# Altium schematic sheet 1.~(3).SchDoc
size 420 x 297 mm
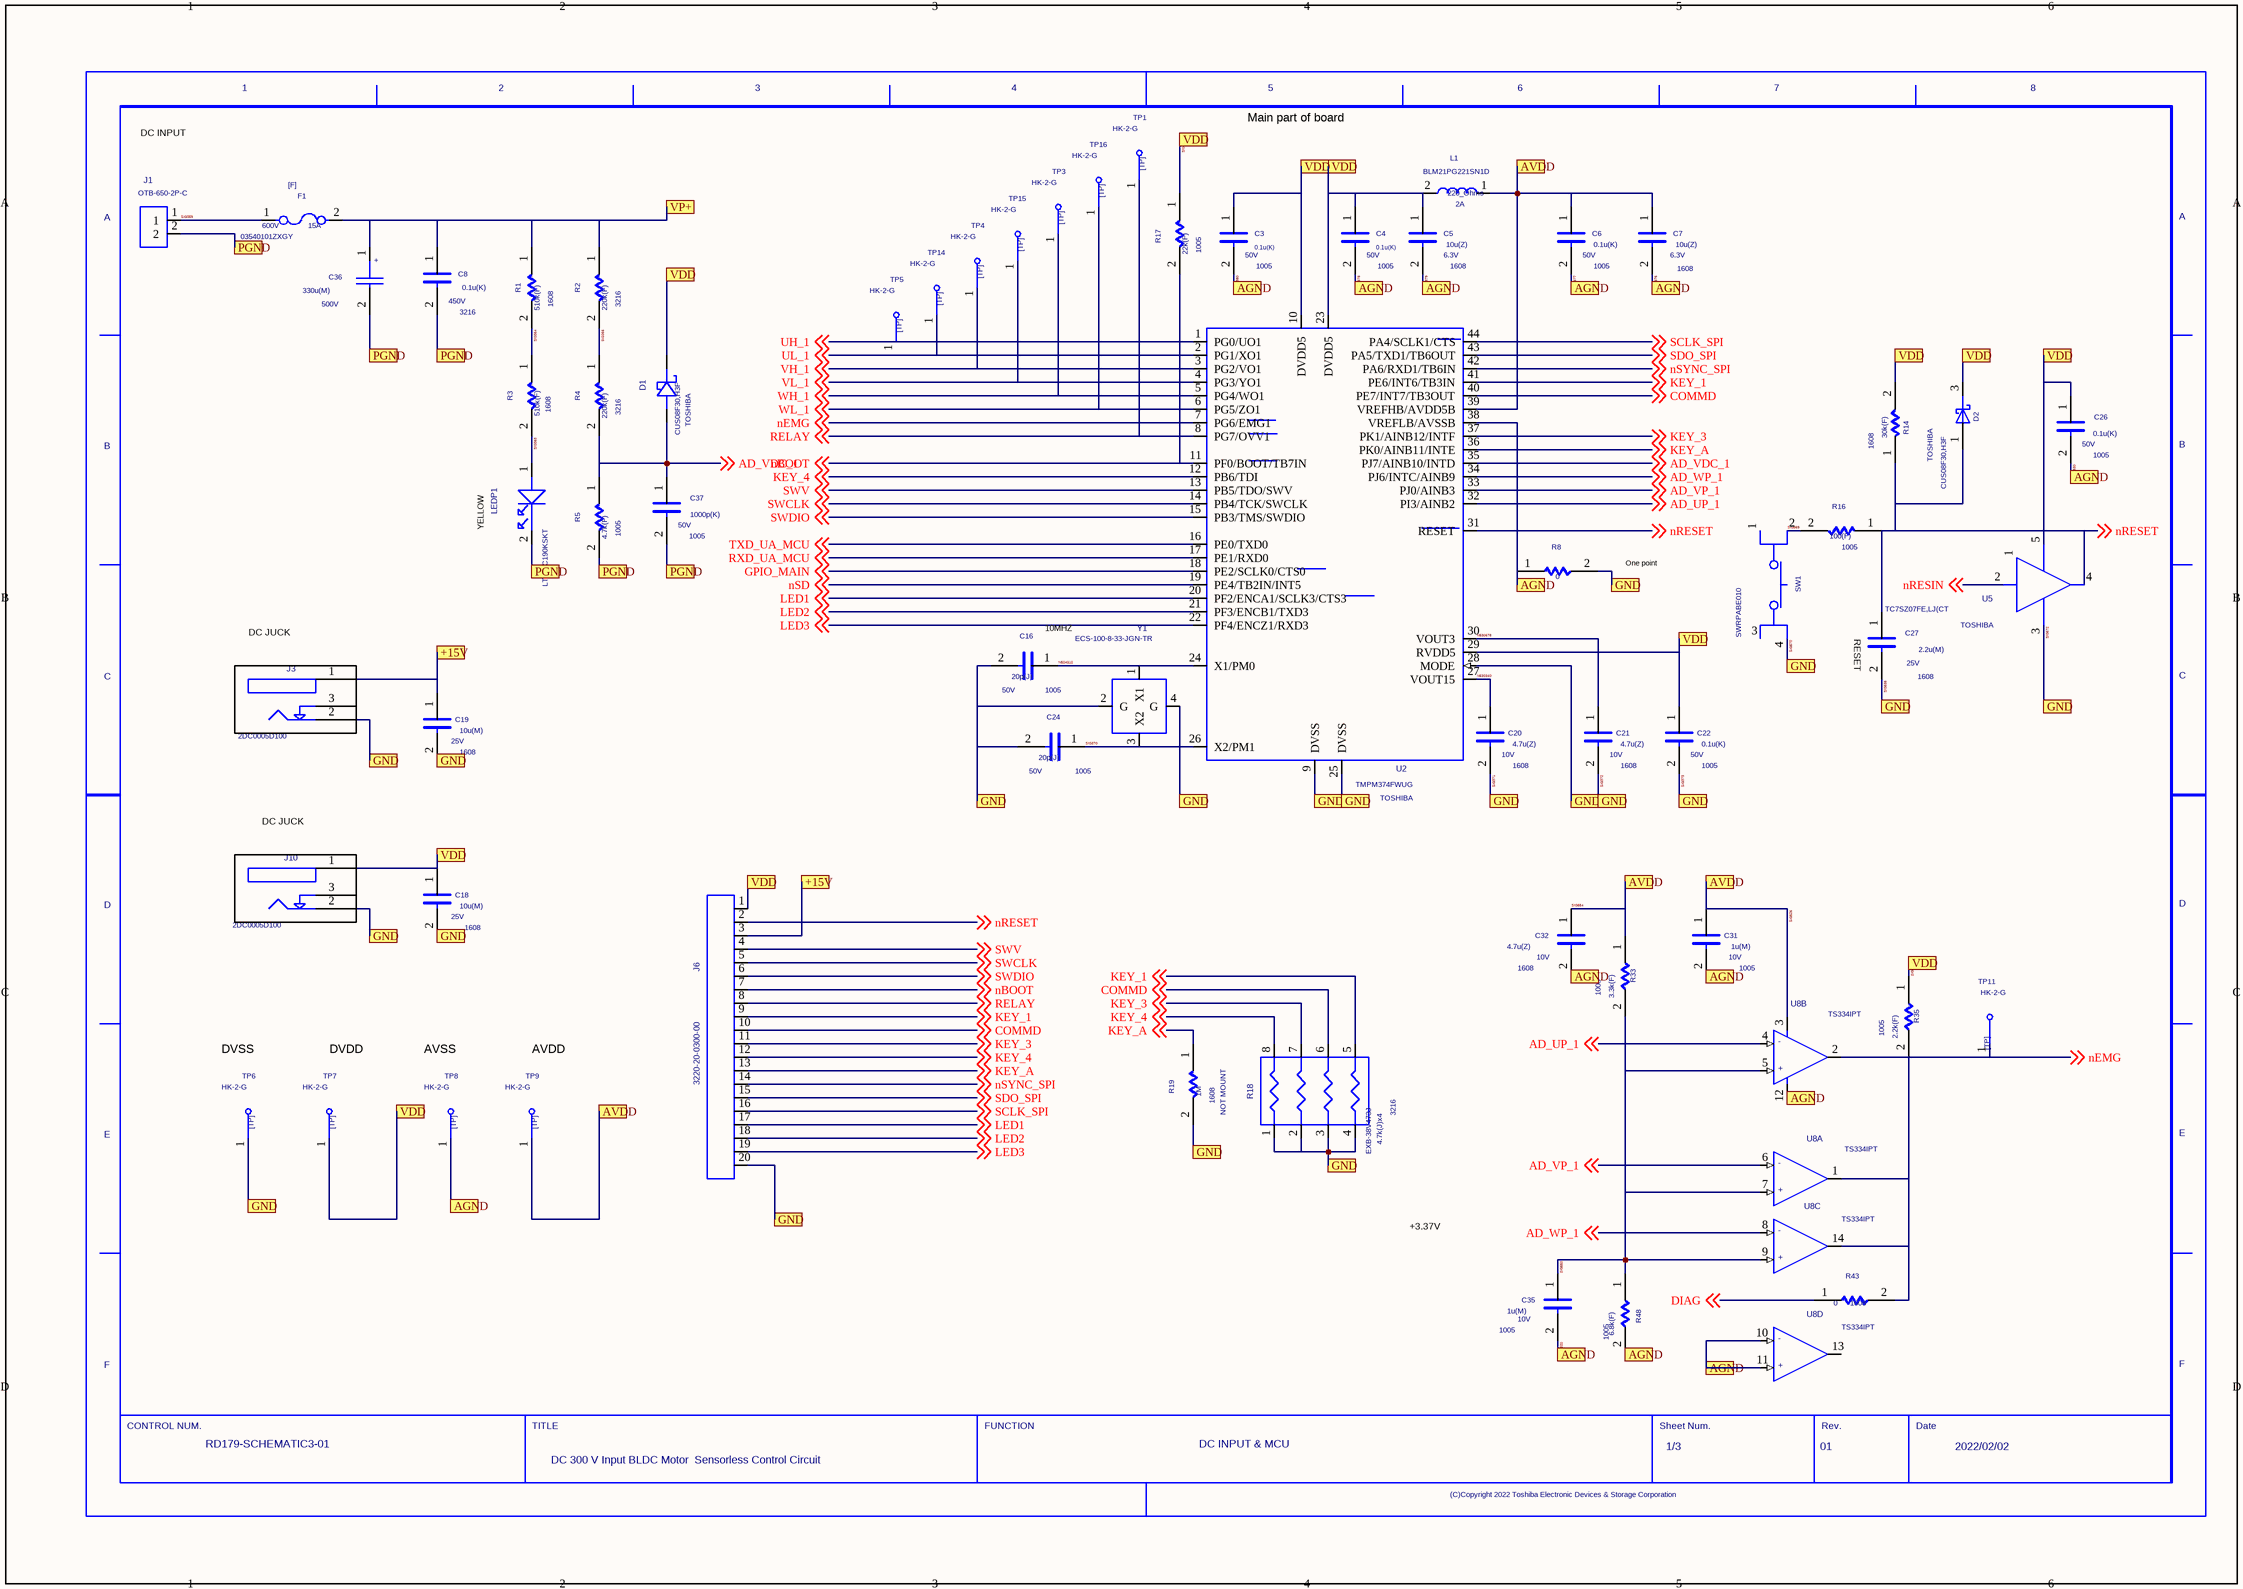
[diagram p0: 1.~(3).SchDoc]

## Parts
C3  SIZECODESMD: 1005  VAL2: 50V  VAL1: 0.1u(K)  (hidden comment: C)
C4  SIZECODESMD: 1005  VAL2: 50V  VAL1: 0.1u(K)  (hidden comment: C)
C5  SIZECODESMD: 1608  VAL2: 6.3V  VAL1: 10u(Z)  (hidden comment: C)
C6  SIZECODESMD: 1005  VAL2: 50V  VAL1: 0.1u(K)  (hidden comment: C)
C7  SIZECODESMD: 1608  VAL2: 6.3V  VAL1: 10u(Z)  (hidden comment: C)
C8  SIZECODESMD: 3216  VAL2: 450V  VAL1: 0.1u(K)  (hidden comment: C)
C16  SIZECODESMD: 1005  VAL2: 50V  VAL1: 20p(J)  (hidden comment: C)
C18  SIZECODESMD: 1608  VAL2: 25V  VAL1: 10u(M)  (hidden comment: C)
C19  SIZECODESMD: 1608  VAL2: 25V  VAL1: 10u(M)  (hidden comment: C)
C20  SIZECODESMD: 1608  VAL2: 10V  VAL1: 4.7u(Z)  (hidden comment: C)
C21  SIZECODESMD: 1608  VAL2: 10V  VAL1: 4.7u(Z)  (hidden comment: C)
C22  SIZECODESMD: 1005  VAL2: 50V  VAL1: 0.1u(K)  (hidden comment: C)
C24  SIZECODESMD: 1005  VAL2: 50V  VAL1: 20p(J)  (hidden comment: C)
C26  SIZECODESMD: 1005  VAL2: 50V  VAL1: 0.1u(K)  (hidden comment: C)
C27  SIZECODESMD: 1608  VAL2: 25V  VAL1: 2.2u(M)  (hidden comment: C)
C31  SIZECODESMD: 1005  VAL2: 10V  VAL1: 1u(M)  (hidden comment: C)
C32  SIZECODESMD: 1608  VAL2: 10V  VAL1: 4.7u(Z)  (hidden comment: C)
C35  SIZECODESMD: 1005  VAL2: 10V  VAL1: 1u(M)  (hidden comment: C)
C36  VAL2: 500V  VAL1: 330u(M)  (hidden comment: CP)
C37  SIZECODESMD: 1005  VAL2: 50V  VAL1: 1000p(K)  (hidden comment: C)
D1  USERCOMPTEXT3: TOSHIBA  VAL3: CUS08F30,H3F  (hidden comment: CUS08F30)
D2  USERCOMPTEXT3: TOSHIBA  VAL3: CUS08F30,H3F  (hidden comment: SBD)
F1  VAL3: 03540101ZXGY  VAL2: 15A  VAL1: 600V  (hidden comment: F)
J1  OTB-650-2P-C
J3  VAL3: 2DC0005D100  (hidden comment: DCJACK)
J6  3220-20-0300-00
J10  VAL3: 2DC0005D100  (hidden comment: DCJACK)
L1  VAL3: BLM21PG221SN1D  VAL2: 2A  VAL1: 220_Ohms  (hidden comment: L)
LEDP1  LTST-C190KSKT  [LED]
R1  SIZECODESMD: 1608  VAL1: 510k(F)  (hidden comment: R)
R2  SIZECODESMD: 3216  VAL1: 220k(F)  (hidden comment: R)
R3  SIZECODESMD: 1608  VAL1: 510k(F)  (hidden comment: R)
R4  SIZECODESMD: 3216  VAL1: 220k(F)  (hidden comment: R)
R5  SIZECODESMD: 1005  VAL1: 4.7k(F)  (hidden comment: R)
R8  VAL1: 0  (hidden comment: R)
R14  SIZECODESMD: 1608  VAL1: 30k(F)  (hidden comment: R)
R16  SIZECODESMD: 1005  VAL1: 100(F)  (hidden comment: R)
R17  SIZECODESMD: 1005  VAL1: 22k(F)  (hidden comment: R)
R18  SIZECODESMD: 3216  VAL1: 4.7k(J)x4  (hidden comment: EXB-38V473J)
R19  NOTMOUNT: NOT MOUNT  SIZECODESMD: 1608  VAL1: 1M  (hidden comment: R)
R33  SIZECODESMD: 1005  VAL1: 3.3k(F)  (hidden comment: R)
R35  SIZECODESMD: 1005  VAL1: 2.2k(F)  (hidden comment: R)
R43  SIZECODESMD: 1608  VAL1: 0  (hidden comment: R)
R48  SIZECODESMD: 1005  VAL1: 6.8k(F)  (hidden comment: R)
SW1  SWRPABE010
TP1  VAL3: HK-2-G  (hidden comment: TP)
TP3  VAL3: HK-2-G  (hidden comment: TP)
TP4  VAL3: HK-2-G  (hidden comment: TP)
TP5  VAL3: HK-2-G  (hidden comment: TP)
TP6  VAL3: HK-2-G  (hidden comment: TP)
TP7  VAL3: HK-2-G  (hidden comment: TP)
TP8  VAL3: HK-2-G  (hidden comment: TP)
TP9  VAL3: HK-2-G  (hidden comment: TP)
TP11  VAL3: HK-2-G  (hidden comment: TP)
TP14  VAL3: HK-2-G  (hidden comment: TP)
TP15  VAL3: HK-2-G  (hidden comment: TP)
TP16  VAL3: HK-2-G  (hidden comment: TP)
U2  USERCOMPTEXT3: TOSHIBA  (hidden comment: TMPM374FWUG)
U5  USERCOMPTEXT3: TOSHIBA  VAL3: TC7SZ07FE,LJ(CT  (hidden comment: SN74LVC1G07DRLR_1)
U8  VAL3: TS334IPT  (hidden comment: LMV339IPT_2)  (parts A,B,C,D of 4)
U?  DATE: 2022/02/02  FUNCTION: DC INPUT & MCU  TITLE: DC 300 V Input BLDC Motor / Sensorless Control Circuit  DRAWINGNUMBER: RD179-SCHEMATIC3-01  REVISION: 01  SHEETNUMBER: 1/3  (hidden comment: WAKU_DEF100)
Y1  VAL3: ECS-100-8-33-JGN-TR  (hidden comment: XTAL_ECS_100_8_33_10_000MHZ)

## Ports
+15V, AGND, AVDD, GND, PGND, VDD, VP+

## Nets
+15V: C19.1 J3.1(+5V) J6.3 ; port +15V
AD_UP_1: U2.32(PI3/AINB2) U8.4(IN-) ; off-sheet AD_UP_1
AD_VDC_1: C37.1 D1.1(ANODE) R4.2 R5.1 U2.35(PJ7/AINB10/INTD) ; off-sheet AD_VDC_1
AD_VP_1: U2.33(PJ0/AINB3) U8.6 ; off-sheet AD_VP_1
AD_WP_1: U2.34(PJ6/INTC/AINB9) U8.8 ; off-sheet AD_WP_1
COMMD: J6.10 R18.6 U2.40(PE7/INT7/TB3OUT) ; off-sheet COMMD
DIAG: R43.1 ; off-sheet DIAG
GPIO_MAIN: U2.18(PE2/SCLK0/CTS0) ; off-sheet GPIO_MAIN
KEY_1: J6.9 R18.5 U2.41(PE6/INT6/TB3IN) ; off-sheet KEY_1
KEY_3: J6.11 R18.7 U2.37(PK1/AINB12/INTF) ; off-sheet KEY_3
KEY_4: J6.12 R18.8 U2.12(PB6/TDI) ; off-sheet KEY_4
KEY_A: J6.13 R19.1 U2.36(PK0/AINB11/INTE) ; off-sheet KEY_A
LED1: J6.17 U2.20(PF2/ENCA1/SCLK3/CTS3) ; off-sheet LED1
LED2: J6.18 U2.21(PF3/ENCB1/TXD3) ; off-sheet LED2
LED3: J6.19 U2.22(PF4/ENCZ1/RXD3) ; off-sheet LED3
N524312: C16.1 U2.24(X1/PM0) Y1.1(X1)
N530340: C20.1 U2.27(VOUT15)
N530678: C21.1 U2.30(VOUT3)
nBOOT: J6.7 R17.2 U2.11(PF0/BOOT/TB7IN) ; off-sheet nBOOT
nEMG: R35.2 R43.2 TP11.1 U2.7(PG6/EMG1) U8.1 U8.2(OUT) U8.14 ; off-sheet nEMG
nRESET: C27.1 D2.1(A) J6.2 R14.1 R16.1 U2.31(RESET) U5.4(OUTY) ; off-sheet nRESET
nSD: U2.19(PE4/TB2IN/INT5) ; off-sheet nSD
nSYNC_SPI: J6.14 U2.42(PA6/RXD1/TB6IN) ; off-sheet nSYNC_SPI
PGND: C8.2 C36.2 C37.2 J1.2 LEDP1.2(Cathode) R5.2 ; port PGND
RELAY: J6.8 TP1.1 U2.8(PG7/OVV1) ; off-sheet RELAY
RXD_UA_MCU: U2.17(PE1/RXD0) ; off-sheet RXD_UA_MCU
SCLK_SPI: J6.16 U2.44(PA4/SCLK1/CTS) ; off-sheet SCLK_SPI
SDO_SPI: J6.15 U2.43(PA5/TXD1/TB6OUT) ; off-sheet SDO_SPI
SIG359: F1.1 J1.1
SIG363: LEDP1.1(Anode) R3.2
SIG364: R1.2 R3.1
SIG366: R2.2 R4.1
SIG369: C3.1 C4.1 C5.1 C18.1 C22.1 C26.1 D1.3(CATHODE) D2.3(C) J6.1 J10.1(+5V) L1.2 R14.2 R17.1 R35.1 TP7.1 U2.10(DVDD5) U2.23(DVDD5) U2.29(RVDD5) U5.5(VCC) ; port VDD  [also labelled SIG522]
SIG370: C24.1 U2.26(X2/PM1) Y1.3(X2)
SIG371: C16.2 C18.2 C19.2 C20.2 C21.2 C22.2 C24.2 C27.2 J3.2(GND) J6.20 J10.2(GND) R8.2 R18.1 R18.2 R18.3 R18.4 R19.2 SW1.4 TP6.1 U2.9(DVSS) U2.25(DVSS) U2.28(MODE) U5.3(GND) Y1.2(G) Y1.4(G) ; port GND  [also labelled SIG372, SIG373, SIG535, SIG570, SIG572]
SIG376: C3.2 C4.2 C5.2 C6.2 C7.2 C26.2 C31.2 C32.2 C35.2 R8.1 R48.2 TP8.1 U2.38(VREFLB/AVSSB) U8.10 U8.11 U8.12(GND) ; port AGND  [also labelled SIG377, SIG378, SIG379, SIG380, SIG520, SIG521, SIG530]
SIG526: C6.1 C7.1 C31.1 C32.1 L1.1 R33.1 TP9.1 U2.39(VREFHB/AVDD5B) U8.3(VCC) ; port AVDD  [also labelled SIG554]
SIG553: C35.1 R33.2 R48.1 U8.5(IN+) U8.7 U8.9
SIG569: R16.2 SW1.2
SIG571: U5.2(INA) ; off-sheet nRESIN  [also labelled nRESIN]
SWCLK: J6.5 U2.14(PB4/TCK/SWCLK) ; off-sheet SWCLK
SWDIO: J6.6 U2.15(PB3/TMS/SWDIO) ; off-sheet SWDIO
SWV: J6.4 U2.13(PB5/TDO/SWV) ; off-sheet SWV
TXD_UA_MCU: U2.16(PE0/TXD0) ; off-sheet TXD_UA_MCU
UH_1: TP5.1 U2.1(PG0/UO1) ; off-sheet UH_1
UL_1: TP14.1 U2.2(PG1/XO1) ; off-sheet UL_1
VH_1: TP4.1 U2.3(PG2/VO1) ; off-sheet VH_1
VL_1: TP15.1 U2.4(PG3/YO1) ; off-sheet VL_1
VP+: C8.1 C36.1 F1.2 R1.1 R2.1 ; port VP+
WH_1: TP3.1 U2.5(PG4/WO1) ; off-sheet WH_1
WL_1: TP16.1 U2.6(PG5/ZO1) ; off-sheet WL_1

Not connected (* = marked no-connect by the designer): J3 3(NC); J10 3(NC); SW1 1 3; U5 1; U8 13

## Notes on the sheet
- DC INPUT
  120V-340V
- Main part of board
- (near LEDP1) YELLOW
- One point
  ground
- (near J3) DC JUCK
  +15V
- (near C16) 10MHZ
- (near C27) RESET
- (near J10) DC JUCK
  +5V
- DVSS
- DVDD
- AVSS
- AVDD
- +3.37V
  (2.89A)

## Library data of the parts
C3 C4 C6 C16 C22 C24 C26 C31 C35 C37 = C: OriginalSymbolOrigin: (2540,7620); COMP: CRC-1005-DEF
C5 C7 C18-C21 C27 C32 = C: OriginalSymbolOrigin: (2540,7620); COMP: CRC-1608-DEF
C8 = C: OriginalSymbolOrigin: (2540,7620); COMP: CC-3216-DEF
C36 = CP: SAVEAREA0: -1450,-153,20294,13055; SAVECOUNT: 52; TIME: 15:02:55; UPDATEUSER: fukuda-y; UPDATETIME: 16:13:42; OriginalSymbolOrigin: (2540,10160); COMP: DDC-3000-00
D1 = DIODE_SB1003M3: COMP: CD-USC-05; TIME: 16:32:01; UPDATEUSER: t5459927; SAVECOUNT: 1; OriginalSymbolOrigin: (0,0); INSTANCENAME: I16849034
D2 = SBD: SAVEAREA0: -4630,-153,17114,13055; TIME: 14:49:55; UPDATEUSER: fukuda-y; UPDATETIME: 08:16:22; SAVECOUNT: 9; OriginalSymbolOrigin: (5080,5080); COMP: CD-USC-05
F1 = F: OriginalSymbolOrigin: (2540,5080); COMP: DFU-3512-00
J1 = OTB_650_2P_C: COMP: OTB-650-2P_R00; TIME: 16:32:00; UPDATEUSER: t5459927; SAVECOUNT: 1; SAVEAREA0: -4443,-7788,6738,409; OriginalSymbolOrigin: (0,0); INSTANCENAME: I00689
J3 = DCJACK: COMP: 2DC-0005D100_R00; ORDER: 0; TIME: 16:32:01; UPDATEUSER: t5459927; SAVECOUNT: 1; SAVEAREA0: -1163,-13964,20286,1761; OriginalSymbolOrigin: (0,0); INSTANCENAME: I16855658
J6 = CON20: COMP: 3220-20-0300-00_R00; TIME: 16:32:01; UPDATEUSER: t5459927; SAVECOUNT: 1; SAVEAREA0: -36272,-54408,42011,2984; OriginalSymbolOrigin: (0,0); INSTANCENAME: I17020784
J10 = DCJACK: COMP: 2DC-0005D100_R00; ORDER: 0; TIME: 16:32:01; UPDATEUSER: t5459927; SAVECOUNT: 1; SAVEAREA0: -1163,-13964,20286,1761; OriginalSymbolOrigin: (0,0); INSTANCENAME: I17047111
L1 = L: OriginalSymbolOrigin: (2540,5080); COMP: CL-2125-DEF
LEDP1 = LED_3RED: COMP: LTST-C190_R00; TIME: 16:32:00; UPDATEUSER: t5459927; SAVECOUNT: 1; OriginalSymbolOrigin: (0,0); INSTANCENAME: I16843725
R1 R3 = R: OriginalSymbolOrigin: (5080,5080); VAL2: 250mW; COMP: CRC-1608-DEF
R2 R4 = R: OriginalSymbolOrigin: (5080,5080); VAL2: 250mW; COMP: CR-3216-DEF
R5 = R: OriginalSymbolOrigin: (5080,5080); VAL2: 63mW; COMP: CRC-1005-DEF
R8 = R: OriginalSymbolOrigin: (5080,5080); COMP: CX-0002-75
R14 = R: OriginalSymbolOrigin: (5080,5080); VAL2: 100mW; COMP: CRC-1608-58
R16 R17 R33 R35 = R: OriginalSymbolOrigin: (5080,5080); VAL2: 100mW; COMP: CRC-1005-DEF
R18 = EXB_38V: COMP: CRA-3216-33; TIME: 16:32:00; UPDATEUSER: t5459927; SAVECOUNT: 1; SAVEAREA0: -8920,-20726,20901,1136; OriginalSymbolOrigin: (0,0); VAL2: 63w; INSTANCENAME: I17038151
R19 R43 = R: OriginalSymbolOrigin: (5080,5080); VAL2: 100mW; COMP: CRC-1608-DEF
R48 = R: OriginalSymbolOrigin: (5080,5080); VAL2: 63mW; COMP: CRC-1005-12
SW1 = SWRPABE010: CDBNAME: S3; MONOCODE: E00000387; DEVICENAME: SKRELEE010; SAVECOUNT: 12; SAVEAREA0: -20086,-19151,40623,8833; TIME: 17:27:08; UPDATEUSER: t5459927; UPDATETIME: 11:11:13; OriginalSymbolOrigin: (-2540,-2540); COMP: SKRPABE010_R01
TP1 TP3-TP9 TP11 TP14-TP16 = TP: TIME: 16:12:21; UPDATEUSER: fukuda-y; UPDATETIME: 16:18:11; SAVECOUNT: 2; SAVEAREA0: -242,-92,12810,7836; OriginalSymbolOrigin: (0,7620)
U2 = TMPM374FWUG: TIME: 16:32:00; UPDATEUSER: t5459927; UPDATETIME: 15:11:09; SAVECOUNT: 3; SAVEAREA0: -44310,-81679,90078,-7285; OriginalSymbolOrigin: (0,0)
U5 = SN74LVC1G07DRLR_1: COMP: TC7SZ07FE; ORDER: 0; TIME: 16:32:01; UPDATEUSER: t5459927; UPDATETIME: 09:28:13; SAVECOUNT: 2; SAVEAREA0: -35105,-23290,44922,13600; OriginalSymbolOrigin: (-2540,2540)
U8 = LMV339IPT_2: TIME: 16:31:59; UPDATEUSER: t5459927; UPDATETIME: 15:18:09; SAVECOUNT: 11; SAVEAREA0: -12314,3023,22191,18929; OriginalSymbolOrigin: (0,0); CaptureCellPackProp: LMV339IPT_2A; FUNCN: TS334IPT_2
U? = WAKU_DEF100: PLOTTIME: HH:MM; SAVEAREA0: 147884,-66467,487065,89883; TIME: 14:30:25; UPDATEUSER: t5459927; UPDATETIME: 12:53:04; SAVECOUNT: 7; OriginalSymbolOrigin: (10160,284480)
Y1 = XTAL_ECS_100_8_33_10_000MHZ: COMP: CXL-3225-68; ORDER: 1; TIME: 16:32:00; UPDATEUSER: t5459927; UPDATETIME: 15:12:21; SAVECOUNT: 3; SAVEAREA0: -55012,-32573,65020,22757; OriginalSymbolOrigin: (0,0)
